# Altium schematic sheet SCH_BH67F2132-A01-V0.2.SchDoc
size A4
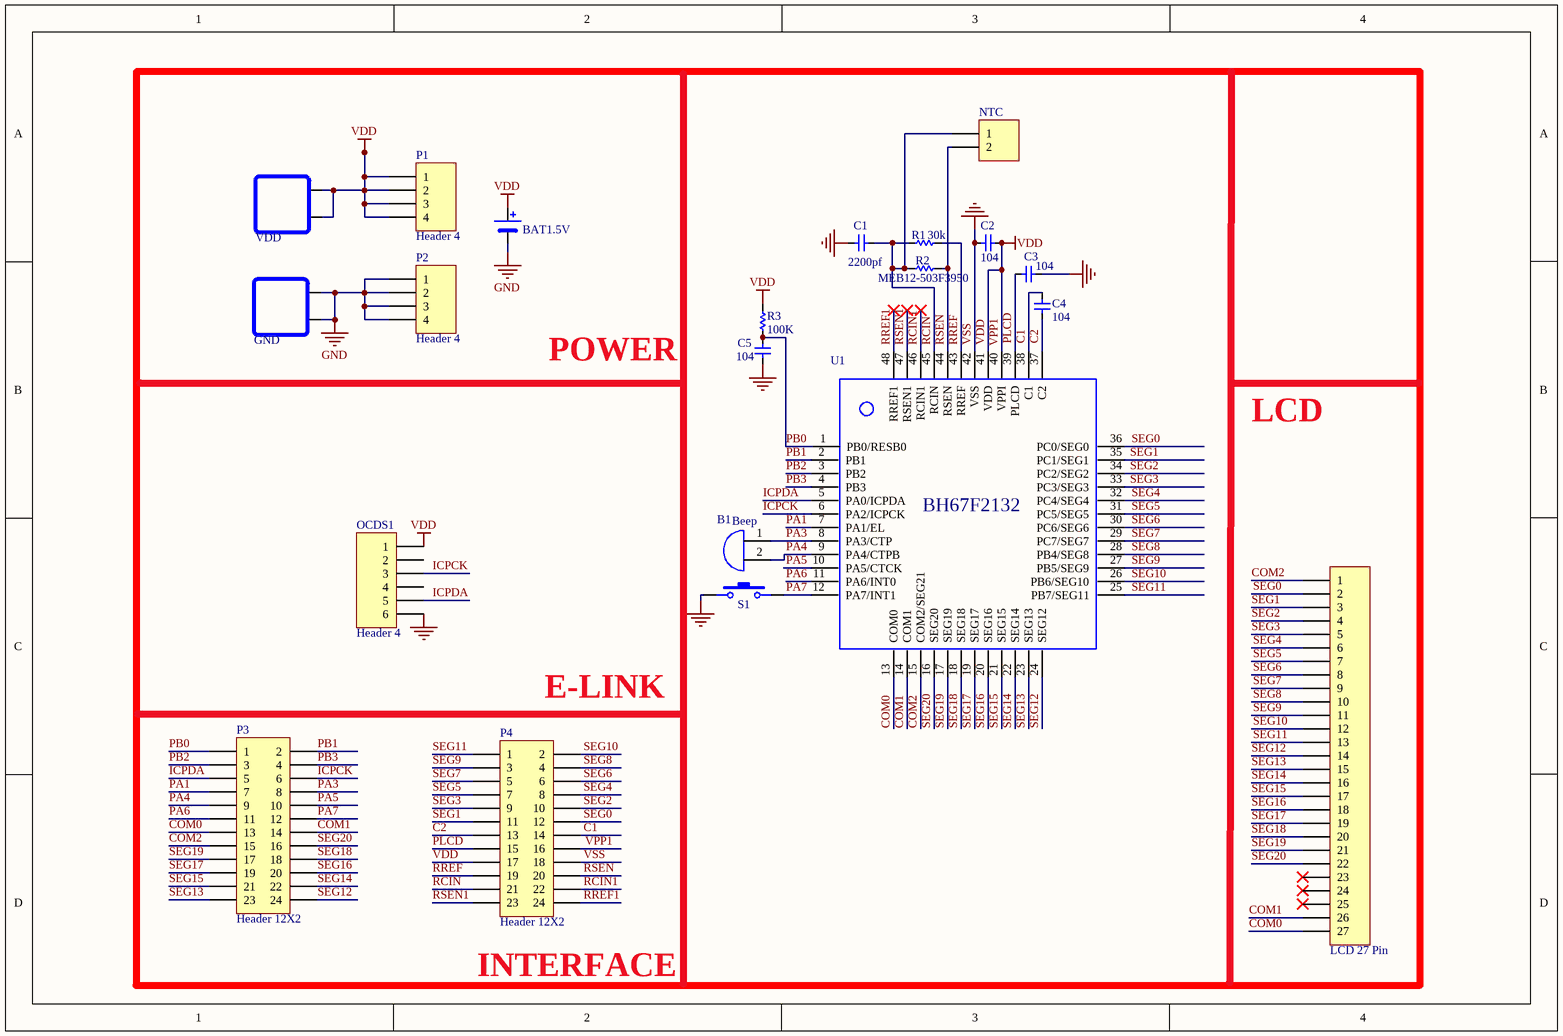
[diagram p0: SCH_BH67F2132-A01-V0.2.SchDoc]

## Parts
B1  Beep  [BEEP]
BAT1.5V  BATTERY(1)  [LR41H]  (value not drawn)
C1  2200pf  [C0603]
C2  104  [C0603]
C3  104  [C0603]
C4  104  [C0603]
C5  104  [C0603]
GND  CONNET*2  [CLIP POWER PIN - duplicate]  (value not drawn)  (no BOM)
LCD1  LCD 27 Pin  [LCD 27 Pin]
NTC  NTC-Header  [NTC]  (value not drawn)
OCDS1  Header 4  [HDR1X6]
P1  Header 4  [HDR1X4]
P2  Header 4  [HDR1X4]
P3  Header 12X2  [HDR2X12]
P4  Header 12X2  [HDR2X12]
R1  30k  [R0603]
R2  MEB12-503F3950  [R0603]
R3  100K  [R0603]
S1  Switch  [AN66]  (value not drawn)
U1  BH67F2132_48LQFP  [LQFP_48]  (value not drawn)
VDD  CONNET*2  [CLIP POWER PIN - duplicate]  (value not drawn)  (no BOM)

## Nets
VDD: BAT1.5V.1(+) C2.1 OCDS1.1 P1.1 P1.2 P1.3 P1.4 P4.16 P4.17 R3.1 U1.40(VPPI) U1.41(VDD) VDD.1 VDD.2  [also labelled VPP1]
VSS: BAT1.5V.2(-) C1.1 C2.2 C3.1 C5.2 GND.1 GND.2 OCDS1.6 P2.1 P2.2 P2.3 P2.4 P4.18 S1.2 U1.42(VSS)  [also labelled GND]
C1: C4.2 P4.14 U1.38(C1)
C2: C4.1 P4.13 U1.37(C2)
COM0: LCD1.27 P3.13 U1.13(COM0)
COM1: LCD1.26 P3.14 U1.14(COM1)
COM2: LCD1.1 P3.15 U1.15(COM2/SEG21)
ICPCK: OCDS1.3 P3.6 U1.6(PA2/ICPCK)
ICPDA: OCDS1.5 P3.5 U1.5(PA0/ICPDA)
PA1: P3.7 U1.7(PA1/EL)
PA3: B1.1 P3.8 U1.8(PA3/CTP)
PA4: B1.2 P3.9 U1.9(PA4/CTPB)
PA5: P3.10 U1.10(PA5/CTCK)
PA6: P3.11 U1.11(PA6/INT0)
PA7: P3.12 S1.1 U1.12(PA7/INT1)
PB0: C5.1 P3.1 R3.2 U1.1(PB0/RESB0)
PB1: P3.2 U1.2(PB1)
PB2: P3.3 U1.3(PB2)
PB3: P3.4 U1.4(PB3)
PLCD: C3.2 P4.15 U1.39(PLCD)
RCIN: C1.2 NTC.1 P4.21 R1.2 R2.2 U1.45(RCIN)
RCIN1: P4.22 U1.46(RCIN1)
RREF: P4.19 R1.1 U1.43(RREF)
RREF1: P4.24 U1.48(RREF1)
RSEN: NTC.2 P4.20 R2.1 U1.44(RSEN)
RSEN1: P4.23 U1.47(RSEN1)
SEG0: LCD1.2 P4.12 U1.36(PC0/SEG0)
SEG1: LCD1.3 P4.11 U1.35(PC1/SEG1)
SEG2: LCD1.4 P4.10 U1.34(PC2/SEG2)
SEG3: LCD1.5 P4.9 U1.33(PC3/SEG3)
SEG4: LCD1.6 P4.8 U1.32(PC4/SEG4)
SEG5: LCD1.7 P4.7 U1.31(PC5/SEG5)
SEG6: LCD1.8 P4.6 U1.30(PC6/SEG6)
SEG7: LCD1.9 P4.5 U1.29(PC7/SEG7)
SEG8: LCD1.10 P4.4 U1.28(PB4/SEG8)
SEG9: LCD1.11 P4.3 U1.27(PB5/SEG9)
SEG10: LCD1.12 P4.2 U1.26(PB6/SEG10)
SEG11: LCD1.13 P4.1 U1.25(PB7/SEG11)
SEG12: LCD1.14 P3.24 U1.24(SEG12)
SEG13: LCD1.15 P3.23 U1.23(SEG13)
SEG14: LCD1.16 P3.22 U1.22(SEG14)
SEG15: LCD1.17 P3.21 U1.21(SEG15)
SEG16: LCD1.18 P3.20 U1.20(SEG16)
SEG17: LCD1.19 P3.19 U1.19(SEG17)
SEG18: LCD1.20 P3.18 U1.18(SEG18)
SEG19: LCD1.21 P3.17 U1.17(SEG19)
SEG20: LCD1.22 P3.16 U1.16(SEG20)

Not connected (* = marked no-connect by the designer): LCD1 23* 24* 25*; OCDS1 2 4; S1 3 4

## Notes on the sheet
- POWER
- LCD
- (near P4) E-LINK
- (near P4) INTERFACE

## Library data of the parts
BAT1.5V = BATTERY(1): Singlecell Battery
C1-C5 = CAP(1)
GND VDD = CONNET*2: 2CONNET*2.54
NTC = Header 2: Header, 2-Pin
OCDS1 = Header 6: Header, 6-Pin
P1 P2 = Header 4: Header, 4-Pin
P3 P4 = Header 12X2: Header, 12-Pin, Dual row
R1 R3 = RES(1)
R2 = RES(1): LINGEE NTC
S1 = Switch_4P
